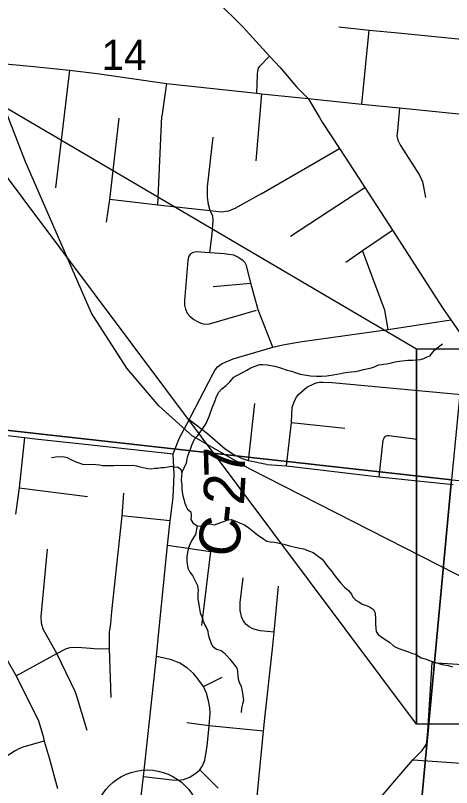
# Model space of a CAD drawing. Extents: x 0 to 43.4, y -8.1 to 22.
# Drawn here: x 7.249 to 7.853, y 17.842 to 18.91 of the extents above; entities that cross this region are included whole.
import ezdxf

# ---------------------------------------------------------------- set-up
doc = ezdxf.new("R2010")
doc.units = 0
for name, color, linetype in [('GM_X_City_Street', 7, 'Continuous'), ('GM_X_Corporation', 7, 'Continuous'), ('GM_X_County_Road', 7, 'Continuous'), ('GM_X_County_Road_Text', 7, 'Continuous'), ('GM_X_Minor_River', 7, 'Continuous'), ('GM_X_Rail_Line', 7, 'Continuous'), ('GM_X_Section_Text', 7, 'Continuous'), ('GM_X_State_Route', 7, 'Continuous'), ('GM_X_Township_Road', 7, 'Continuous'), ('GM_X_Unincorporated', 7, 'Continuous'), ('SH_Masking', 7, 'Continuous'), ('SH_Text', 7, 'Continuous')]:
    doc.layers.add(name, color=color, linetype=linetype)

msp = doc.modelspace()

# ---------------------------------------------------------------- linework, layer by layer
at = {"layer": 'GM_X_City_Street'}
for p, q in [((7.7288, 18.7873), (7.739, 18.8897)), ((7.4583, 18.8156), (7.4518, 18.7707)), ((7.5901, 18.8016), (7.582, 18.7088)), ((7.5895, 18.6631), (7.6979, 18.7257)), ((7.6302, 18.6047), (7.7331, 18.6717)), ((7.5186, 18.5817), (7.5214, 18.6076)), ((7.523, 18.5351), (7.5752, 18.5397)), ((7.6316, 18.3469), (7.7051, 18.339))]:
    msp.add_line(p, q, dxfattribs=at)
for points in [[(7.697, 18.894), (7.739, 18.8897), (7.7789, 18.8856), (7.9083, 18.8729), (7.9308, 18.8707), (7.9486, 18.8682), (7.9647, 18.8635), (7.9834, 18.8608), (8.1366, 18.849)], [(7.5834, 18.8023), (7.5842, 18.8281), (7.5847, 18.8338), (7.5856, 18.837), (7.5875, 18.8398), (7.601, 18.8536)], [(7.7808, 18.782), (7.7779, 18.7501), (7.7773, 18.7434), (7.7787, 18.7375), (7.7822, 18.7299), (7.8087, 18.689), (7.8125, 18.6797), (7.8142, 18.6726), (7.8168, 18.658)], [(7.7067, 18.5687), (7.7296, 18.5845), (7.7711, 18.6129)], [(7.6056, 18.4508), (7.5851, 18.5028), (7.5752, 18.5397), (7.5692, 18.564), (7.5674, 18.5677), (7.5645, 18.5704), (7.5601, 18.5736), (7.5571, 18.5757), (7.5515, 18.5784), (7.5447, 18.5792), (7.5384, 18.5799), (7.5186, 18.5817), (7.4995, 18.5827), (7.4952, 18.582), (7.4911, 18.5796), (7.4889, 18.5758), (7.4879, 18.5708), (7.4834, 18.5154), (7.4834, 18.5091), (7.4847, 18.5036), (7.4872, 18.4981), (7.4907, 18.4938), (7.4961, 18.4892), (7.5014, 18.4865), (7.5059, 18.4844), (7.5115, 18.483), (7.5178, 18.4834), (7.5832, 18.5024)], [(7.7651, 18.4756), (7.7607, 18.5022), (7.7571, 18.5118), (7.7296, 18.5845)], [(7.6243, 18.2867), (7.6316, 18.3469), (7.6324, 18.3674), (7.6356, 18.3767), (7.6384, 18.3819), (7.6417, 18.3862), (7.6526, 18.3958), (7.6622, 18.4001), (7.6656, 18.4015), (7.67, 18.4026), (7.6749, 18.4028), (7.6876, 18.4019), (7.8667, 18.3854)], [(7.7529, 18.2718), (7.7583, 18.3222), (7.759, 18.3244), (7.76, 18.3263), (7.761, 18.3274), (7.7625, 18.3282), (7.7643, 18.3287), (7.7661, 18.3288), (7.8051, 18.3235)], [(7.5969, 18.2886), (7.6243, 18.2867), (7.7529, 18.2718), (7.855, 18.2608)]]:
    msp.add_lwpolyline(points, dxfattribs=at)
at = {"layer": 'GM_X_Corporation'}
for points in [[(7.955, 19.3167), (7.9506, 19.2736), (7.8526, 18.2674), (6.8431, 18.3799), (6.9413, 19.3833), (7.3067, 19.3445), (7.3077, 19.3879)], [(8.9, 18.6915), (8.9, 19.1875), (7.9506, 19.2736), (7.8526, 18.2674), (8.8482, 18.1867)], [(6.8431, 18.3799), (7.8526, 18.2674), (7.7575, 17.2431), (6.7271, 17.3517)], [(8.8482, 18.1867), (8.7485, 17.1931), (7.7575, 17.2431), (7.8526, 18.2674)]]:
    msp.add_lwpolyline(points, close=True, dxfattribs=at)
at = {"layer": 'GM_X_County_Road'}
msp.add_line((7.8199, 17.92), (7.826, 18.0147), dxfattribs=at)
for points in [[(6.9786, 18.8698), (7.1101, 18.8565), (7.1805, 18.8478), (7.2702, 18.8398), (7.3244, 18.8344), (7.3587, 18.8301), (7.3625, 18.8295)], [(7.3625, 18.8295), (7.4583, 18.8156), (7.5834, 18.8023), (7.5901, 18.8016), (7.6544, 18.7948)], [(7.6544, 18.7948), (7.7288, 18.7873), (7.7808, 18.782), (7.8994, 18.77), (7.9947, 18.759)], [(7.6352, 18.457), (7.6462, 18.4589), (7.7651, 18.4756), (7.8521, 18.4886)], [(7.6056, 18.4508), (7.6192, 18.4542), (7.6352, 18.457)], [(7.5228, 18.4144), (7.5253, 18.4189), (7.5289, 18.4238), (7.5354, 18.4282), (7.5508, 18.4348), (7.6056, 18.4508)], [(7.4678, 18.3033), (7.4763, 18.3256), (7.4897, 18.3506), (7.4923, 18.3553), (7.5228, 18.4144)], [(7.2329, 18.3296), (7.2387, 18.3289), (7.262, 18.326), (7.2766, 18.3243), (7.3541, 18.3158)], [(7.3541, 18.3158), (7.3582, 18.3153), (7.4678, 18.3033)], [(7.4132, 17.5854), (7.4215, 17.6596), (7.4203, 17.7001), (7.4178, 17.7283), (7.4167, 17.7471), (7.4194, 17.7952), (7.4265, 17.8569), (7.4448, 18.0229), (7.4467, 18.0473), (7.4597, 18.177), (7.4634, 18.2108), (7.4675, 18.2428), (7.469, 18.2748), (7.4678, 18.3033)], [(7.826, 18.0147), (7.9172, 18.0088), (8.0269, 17.9997), (8.0392, 18.0005), (8.0498, 18.0026), (8.0608, 18.0083), (8.0714, 18.0165), (8.0874, 18.0401), (8.0942, 18.0548), (8.0988, 18.0612), (8.106, 18.0688), (8.1257, 18.0883)], [(7.2249, 18.0398), (7.2504, 17.9963), (7.2813, 17.934), (7.2875, 17.9141), (7.289, 17.9061), (7.296, 17.8829), (7.3076, 17.8407)], [(7.7992, 17.8803), (7.8124, 17.8932), (7.8181, 17.902), (7.8192, 17.9097), (7.8199, 17.92)], [(7.707, 17.2463), (7.7156, 17.3082), (7.7212, 17.359), (7.7233, 17.38), (7.7234, 17.3962), (7.7199, 17.416), (7.7156, 17.4332), (7.6975, 17.4916), (7.6871, 17.529), (7.6744, 17.5718), (7.6604, 17.6215), (7.6587, 17.6304), (7.6577, 17.6397), (7.658, 17.6496), (7.6589, 17.6583), (7.6607, 17.6668), (7.664, 17.6781), (7.6701, 17.6956), (7.6764, 17.7122), (7.6912, 17.7472), (7.6994, 17.7637), (7.7415, 17.8129), (7.7992, 17.8803)], [(7.7992, 17.8803), (8.041, 17.8637), (8.0441, 17.8635)]]:
    msp.add_lwpolyline(points, dxfattribs=at)
at = {"layer": 'GM_X_Minor_River'}
for points in [[(7.4795, 18.2771), (7.4831, 18.2839), (7.486, 18.291), (7.4873, 18.299), (7.4894, 18.3043), (7.491, 18.3084), (7.4935, 18.3156), (7.4971, 18.3235), (7.5018, 18.3287), (7.505, 18.3335), (7.5086, 18.3384), (7.5133, 18.3455), (7.5153, 18.35), (7.5174, 18.3549), (7.519, 18.3591), (7.5215, 18.367), (7.5252, 18.376), (7.5272, 18.3813), (7.5304, 18.3881), (7.5348, 18.3933), (7.541, 18.398), (7.5461, 18.4029), (7.5516, 18.4096), (7.5558, 18.4117), (7.5655, 18.4168), (7.5697, 18.4193), (7.5751, 18.4226), (7.5797, 18.4244), (7.5874, 18.4268), (7.5916, 18.4271), (7.5984, 18.4265), (7.6079, 18.4247), (7.6147, 18.423), (7.6256, 18.4193), (7.6316, 18.4176), (7.6365, 18.4159), (7.6433, 18.4138), (7.6577, 18.4115), (7.6661, 18.4109), (7.6729, 18.4107), (7.6802, 18.4113), (7.6889, 18.4126), (7.6993, 18.4146), (7.7035, 18.4156), (7.7092, 18.4162), (7.7145, 18.4168), (7.7195, 18.4174), (7.7241, 18.4184), (7.731, 18.4202), (7.7401, 18.4218), (7.7447, 18.4232), (7.7524, 18.4264), (7.7627, 18.428), (7.7681, 18.429), (7.7731, 18.4304), (7.7773, 18.4311), (7.7845, 18.432), (7.7922, 18.4329), (7.799, 18.4331), (7.8051, 18.4337), (7.8097, 18.434), (7.8143, 18.4354), (7.8193, 18.4375), (7.8235, 18.4389), (7.8263, 18.4434), (7.8298, 18.4475), (7.8384, 18.4541), (7.8403, 18.4556)], [(7.2995, 18.2982), (7.3052, 18.2991), (7.3151, 18.2996), (7.3211, 18.2983), (7.326, 18.2955), (7.3331, 18.2923), (7.3373, 18.291), (7.3422, 18.2893), (7.3608, 18.2888), (7.3657, 18.2883), (7.3699, 18.2874), (7.3764, 18.2872), (7.3855, 18.2874), (7.3912, 18.2876), (7.3977, 18.2874), (7.4019, 18.2877), (7.4068, 18.2872), (7.4117, 18.2878), (7.4167, 18.2869), (7.422, 18.2856), (7.4261, 18.2847), (7.4325, 18.283), (7.4375, 18.2829), (7.442, 18.2835), (7.4466, 18.2838), (7.4512, 18.2844), (7.4554, 18.2847), (7.4607, 18.2856), (7.4649, 18.2863), (7.4691, 18.285), (7.4737, 18.2853), (7.4781, 18.2821), (7.4795, 18.2771), (7.4794, 18.2726), (7.4789, 18.2669), (7.4795, 18.2604), (7.4797, 18.255), (7.4803, 18.2504), (7.4809, 18.2455), (7.4823, 18.2409), (7.4834, 18.2366), (7.4851, 18.2316), (7.4873, 18.227), (7.4921, 18.2231), (7.4924, 18.2185), (7.4922, 18.2128), (7.4951, 18.2081), (7.5007, 18.2038), (7.5076, 18.2032), (7.5141, 18.2057), (7.5183, 18.2067), (7.5247, 18.205), (7.5324, 18.2082), (7.5374, 18.21), (7.5436, 18.2121), (7.5485, 18.2127), (7.5666, 18.205), (7.5725, 18.201), (7.5792, 18.1955), (7.5844, 18.1915), (7.593, 18.1852), (7.5975, 18.1824), (7.6017, 18.1815), (7.6077, 18.1814), (7.6123, 18.1805), (7.6164, 18.1792), (7.621, 18.1783), (7.6285, 18.1762), (7.6365, 18.1745), (7.6429, 18.1731), (7.6482, 18.1719), (7.6561, 18.169), (7.6614, 18.1669), (7.667, 18.163), (7.674, 18.1578), (7.6781, 18.152), (7.6817, 18.1473), (7.6873, 18.1407), (7.6902, 18.1364), (7.6953, 18.1294), (7.6998, 18.1247), (7.7049, 18.1189), (7.7101, 18.1145), (7.7146, 18.1094), (7.7163, 18.1052), (7.7204, 18.1009), (7.7245, 18.0985), (7.7294, 18.0953), (7.7347, 18.0936), (7.7392, 18.0916), (7.7448, 18.088), (7.7473, 18.0834), (7.7475, 18.0742), (7.7477, 18.0681), (7.7479, 18.0624), (7.7485, 18.0578), (7.7515, 18.0536), (7.7563, 18.05), (7.7612, 18.0468), (7.7671, 18.0428), (7.7731, 18.0373)], [(7.5007, 18.2038), (7.4985, 18.1917), (7.4937, 18.1842), (7.4909, 18.1782), (7.4889, 18.1733), (7.4876, 18.1672), (7.4866, 18.1608), (7.4865, 18.1543), (7.4881, 18.1455), (7.4906, 18.1397), (7.4943, 18.135), (7.4979, 18.1277), (7.5012, 18.1215), (7.5021, 18.115), (7.502, 18.1104), (7.5018, 18.1028), (7.5028, 18.0978), (7.5041, 18.089), (7.5051, 18.0837), (7.5079, 18.0771), (7.5093, 18.0721), (7.5111, 18.0675), (7.5136, 18.0629), (7.5158, 18.0582), (7.516, 18.0533), (7.5175, 18.0491), (7.5196, 18.0425), (7.5221, 18.0375), (7.5277, 18.0332), (7.5341, 18.0315), (7.5389, 18.0275), (7.5459, 18.0193), (7.5515, 18.0127), (7.5559, 18.0069), (7.5565, 18.0026), (7.5571, 17.9965), (7.5577, 17.9923), (7.5591, 17.9877), (7.5616, 17.9816), (7.563, 17.975), (7.564, 17.9693), (7.5649, 17.962), (7.5636, 17.9571), (7.562, 17.9515), (7.5618, 17.9457)], [(7.7731, 18.0373), (7.7776, 18.0349), (7.7851, 18.0324), (7.7892, 18.0308), (7.7934, 18.0295), (7.7975, 18.0279), (7.8032, 18.0262), (7.811, 18.0214), (7.8178, 18.0193), (7.8231, 18.0169), (7.8352, 18.0135), (7.8397, 18.0119), (7.8484, 18.0105), (7.8544, 18.0088)]]:
    msp.add_lwpolyline(points, dxfattribs=at)
at = {"layer": 'GM_X_Rail_Line'}
msp.add_lwpolyline([(8.5673, 17.785), (8.3852, 17.869), (7.5731, 18.2825), (7.4939, 18.3285), (7.448, 18.3697), (7.4037, 18.422), (7.3546, 18.498), (7.2632, 18.7074), (7.2074, 18.8505)], dxfattribs=at)
at = {"layer": 'GM_X_State_Route'}
msp.add_line((7.6544, 18.7948), (7.6701, 18.7686), dxfattribs=at)
for points in [[(7.3173, 19.1096), (7.337, 19.088), (7.3546, 19.0676), (7.3683, 19.0539), (7.3928, 19.0322), (7.458, 18.9837), (7.5074, 18.9447), (7.5274, 18.9299), (7.5641, 18.8939), (7.601, 18.8536), (7.6155, 18.8377), (7.6383, 18.8113), (7.6544, 18.7948)], [(7.6701, 18.7686), (7.6738, 18.7624), (7.6979, 18.7257), (7.7248, 18.6846), (7.7331, 18.6717), (7.7711, 18.6129), (7.8405, 18.5055), (7.8521, 18.4886), (7.8734, 18.4576)]]:
    msp.add_lwpolyline(points, dxfattribs=at)
at = {"layer": 'GM_X_Township_Road'}
for p, q in [((7.3244, 18.8344), (7.3047, 18.6712)), ((7.4464, 18.6474), (7.4518, 18.7707)), ((7.572, 18.2938), (7.5806, 18.3729)), ((7.2545, 18.2563), (7.3493, 18.2443)), ((7.4634, 18.2108), (7.3964, 18.2175)), ((7.4597, 18.177), (7.5192, 18.1681)), ((7.5192, 18.1681), (7.5069, 18.0658)), ((7.5097, 17.9816), (7.5355, 17.9943)), ((7.5176, 17.9273), (7.4867, 17.9311)), ((7.5926, 17.9197), (7.5176, 17.9273)), ((7.5046, 17.8661), (7.53, 17.8408))]:
    msp.add_line(p, q, dxfattribs=at)
for points in [[(7.3756, 18.624), (7.38, 18.6551), (7.3929, 18.7679)], [(7.5214, 18.6076), (7.5229, 18.6257), (7.5225, 18.6329), (7.519, 18.6398), (7.5166, 18.6482), (7.5152, 18.6583), (7.5153, 18.6729), (7.5231, 18.7414)], [(7.5895, 18.6631), (7.5532, 18.6427), (7.544, 18.6393), (7.5346, 18.6377), (7.519, 18.6398), (7.4464, 18.6474), (7.38, 18.6551)], [(7.5969, 18.2886), (7.572, 18.2938), (7.5637, 18.2967), (7.5503, 18.3029), (7.5396, 18.3097), (7.5153, 18.3311), (7.4897, 18.3506)], [(7.262, 18.326), (7.2545, 18.2563), (7.2496, 18.2202)], [(7.3988, 18.2489), (7.3964, 18.2175), (7.3825, 18.0852)], [(7.3067, 18.027), (7.2878, 18.0611), (7.2854, 18.0694), (7.2848, 18.0785), (7.2938, 18.1716)], [(7.6074, 18.0569), (7.5881, 18.0586), (7.5781, 18.0614), (7.5728, 18.0641), (7.5686, 18.0675), (7.5669, 18.0696), (7.5649, 18.0725), (7.5625, 18.0765), (7.5602, 18.0868), (7.5603, 18.0979), (7.5645, 18.1321)], [(7.5782, 17.7728), (7.5926, 17.9197), (7.5946, 17.9376), (7.6053, 18.0335), (7.6074, 18.0569), (7.6134, 18.1202)], [(7.3825, 18.0852), (7.3808, 18.0689), (7.3792, 18.0568), (7.3789, 18.0469), (7.3793, 18.0342), (7.3815, 17.9665)], [(7.2504, 17.9963), (7.3067, 18.027), (7.32, 18.0342), (7.3249, 18.0357), (7.3355, 18.0362), (7.3532, 18.0346), (7.3633, 18.0335), (7.3793, 18.0342)], [(7.3488, 17.9205), (7.3337, 17.9697), (7.3315, 17.9754), (7.326, 17.9872), (7.3067, 18.027)], [(7.4265, 17.8569), (7.4665, 17.8523), (7.4748, 17.8522), (7.4819, 17.8528), (7.4909, 17.8562), (7.4995, 17.862), (7.5046, 17.8661), (7.5083, 17.8719), (7.5114, 17.8798), (7.5118, 17.883), (7.5145, 17.8989), (7.5176, 17.9273), (7.5188, 17.9448), (7.5182, 17.9522), (7.5166, 17.9619), (7.5136, 17.9725), (7.5097, 17.9816), (7.502, 17.9923), (7.4956, 17.9997), (7.4873, 18.007), (7.4767, 18.0138), (7.4653, 18.0183), (7.4555, 18.0207), (7.4448, 18.0229)], [(7.289, 17.9061), (7.2608, 17.8979), (7.2549, 17.8959), (7.2489, 17.8928), (7.2348, 17.8834), (7.2269, 17.8803), (7.2023, 17.8802), (7.1774, 17.8799), (7.1646, 17.8795), (7.1562, 17.8807), (7.1418, 17.8776), (7.1316, 17.8742), (7.1271, 17.8727)]]:
    msp.add_lwpolyline(points, dxfattribs=at)
at = {"layer": 'GM_X_Unincorporated'}
msp.add_circle((7.4318, 17.7917), 0.0744, dxfattribs=at)
at = {"layer": 'SH_Masking'}
msp.add_lwpolyline([(7.8046, 18.4489), (9.562, 18.4489), (9.562, 17.9294), (7.8046, 17.9294)], close=True, dxfattribs=at)
at = {"layer": 'SH_Text'}
for points in [[(7.8046, 17.9294), (7.1101, 18.8565), (7.8046, 18.4489)], [(7.8046, 18.4489), (9.562, 18.4489), (9.562, 17.9294), (7.8046, 17.9294)], [(7.8046, 18.4489), (9.562, 18.4489), (9.562, 17.9294), (7.8046, 17.9294)]]:
    msp.add_lwpolyline(points, close=True, dxfattribs=at)

# ---------------------------------------------------------------- texts
at = {"layer": 'GM_X_County_Road_Text'}
for s, rotation, p in [('7', 91.5631, (7.5677, 18.2721)), ('2', 86.3745, (7.5654, 18.2316)), ('-', 83.9783, (7.5628, 18.2058)), ('C', 83.4934, (7.5574, 18.1589))]:
    msp.add_text(s, height=0.0568, rotation=rotation, dxfattribs=at).set_placement(p)
at = {"layer": 'GM_X_Section_Text'}
msp.add_text('14', height=0.04186, rotation=0, dxfattribs=at).set_placement((7.3685, 18.8343))

doc.saveas('drawing.dxf')
